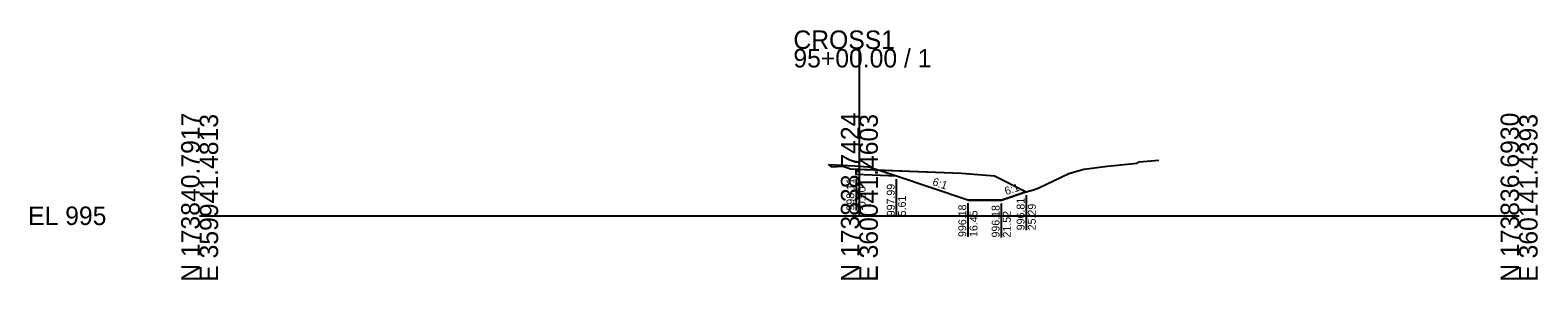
# Model space of a CAD drawing. Extents: x -26 to 1403, y -10 to 11027.
# Drawn here: x -25.7 to 202.8, y 9990.3 to 10028.1 of the extents above; entities that cross this region are included whole.
import ezdxf

# ---------------------------------------------------------------- set-up
doc = ezdxf.new("R2010")
doc.units = 0
for name, color, linetype in [('Default', 7, 'Continuous'), ('P_E_XS_Ground', 7, 'Continuous'), ('P_XS', 7, 'Continuous'), ('P_XS_EAR_CommonGrnd', 7, 'Continuous'), ('P_XS_Lane', 7, 'Continuous'), ('P_XS_Rock', 7, 'Continuous')]:
    doc.layers.add(name, color=color, linetype=linetype)

msp = doc.modelspace()

# ---------------------------------------------------------------- linework, layer by layer
at = {"layer": 'Default'}
for p, q in [((100, 10000), (100, 10025.24)), ((0, 10000), (100, 10000)), ((100, 10000), (200, 10000))]:
    msp.add_line(p, q, dxfattribs=at)
at = {"layer": 'P_E_XS_Ground'}
for p, q in [((95.26, 10007.74), (95.77, 10007.42)), ((95.77, 10007.42), (97.56, 10007.48)), ((97.56, 10007.48), (98.63, 10007.1)), ((134.01, 10007.03), (137.62, 10007.52)), ((137.62, 10007.52), (142.12, 10007.97)), ((142.12, 10007.97), (142.43, 10008.15)), ((142.43, 10008.15), (145.38, 10008.41)), ((98.63, 10007.1), (115.5, 10006.42)), ((115.5, 10006.42), (120.5, 10006.02)), ((120.5, 10006.02), (125.29, 10003.63)), ((127.2, 10004.21), (131.75, 10006.41)), ((131.75, 10006.41), (134.01, 10007.03)), ((125.29, 10003.63), (126.38, 10003.93)), ((126.38, 10003.93), (127.2, 10004.21))]:
    msp.add_line(p, q, dxfattribs=at)
at = {"layer": 'P_XS'}
for p, q in [((95.3, 10007.74), (99.3, 10007.58)), ((99.3, 10007.58), (101.3, 10007.42)), ((105.61, 10005.98), (101.3, 10007.42))]:
    msp.add_line(p, q, dxfattribs=at)
at = {"layer": 'P_XS_EAR_CommonGrnd'}
msp.add_lwpolyline([(99.5, 10007.01), (99.5, 10007.06), (115.5, 10006.42), (120.5, 10006.02), (125.29, 10003.63), (121.52, 10002.37), (116.45, 10002.37), (105.61, 10005.98), (99.5, 10006.23)], close=True, dxfattribs=at)
at = {"layer": 'P_XS_Lane'}
for p, q in [((99.5, 10007.01), (99.5, 10007.06)), ((99.5, 10006.23), (99.5, 10007.01)), ((105.61, 10005.98), (99.5, 10006.23)), ((116.45, 10002.37), (105.61, 10005.98)), ((121.52, 10002.37), (125.29, 10003.63)), ((116.45, 10002.37), (121.52, 10002.37))]:
    msp.add_line(p, q, dxfattribs=at)
at = {"layer": 'P_XS_Rock'}
for p, q in [((99.49, 10005.6), (99.49, 10000.78)), ((105.6, 10005.56), (105.6, 9999.92)), ((125.29, 10003.11), (125.29, 9997.8)), ((116.45, 10001.91), (116.45, 9996.79)), ((121.5, 10001.83), (121.5, 9996.71))]:
    msp.add_line(p, q, dxfattribs=at)

# ---------------------------------------------------------------- texts
at = {"layer": 'Default'}
for s, p in [('CROSS1', (90, 10025.24)), ('95+00.00 / 1', (90, 10022.44)), ('EL 995', (-26, 9998.6))]:
    msp.add_text(s, height=2.8, dxfattribs=at).set_placement(p)
for s, p in [('N 173840.7917', (0, 9990)), ('E 359941.4813', (2.8, 9990)), ('N 173838.7424', (100, 9990)), ('E 360041.4603', (102.8, 9990)), ('N 173836.6930', (200, 9990)), ('E 360141.4393', (202.8, 9990))]:
    msp.add_text(s, height=2.8, rotation=90, dxfattribs=at).set_placement(p)
at = {"layer": 'P_XS_Rock'}
for s, rotation, p in [('998.11', 90, (99.24, 10000.78)), ('6:1', 341.5651, (110.98, 10004.66)), ('-0.50', 90, (100.94, 10000.78)), ('997.99', 90, (105.35, 9999.92)), ('5.61', 90, (107.05, 9999.92)), ('6:1', 18.4349, (122.25, 10003.11)), ('996.18', 90, (116.2, 9996.79)), ('16.45', 90, (117.9, 9996.79)), ('996.18', 90, (121.25, 9996.71)), ('21.52', 90, (122.95, 9996.71)), ('996.81', 90, (125.04, 9997.8)), ('25.29', 90, (126.74, 9997.8))]:
    msp.add_text(s, height=1.2, rotation=rotation, dxfattribs=at).set_placement(p)

doc.saveas('drawing.dxf')
